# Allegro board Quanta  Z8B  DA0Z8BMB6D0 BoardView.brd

Outline 202.63 x 196.03 mm; copper layers: TOP, SVCC, IN1, IN2, SGND, BOTTOM. Coordinates in mm from the lower left corner of the outline.

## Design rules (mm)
constraint set DEFAULT: min track width 0.127
net group DFP-S10W5(5.25)-T2B: nets VCC_SENSE_R VSS_SENSE_R
net group DFP-S20W5(5.25)-T2B: nets DDCCLK DDCDAT
net group W8-T12B: nets +3V_EC +3V_RTC
net group W80-T12B: nets +5V_HDD +5V_ODD
net group DFP-S3.5(3.75)W5(5.25)-T1B: nets VMA_RDQS0 VMA_RDQS1 VMA_RDQS2 VMA_RDQS4 VMA_RDQS5 VMA_RDQS6 VMA_WDQS0 VMA_WDQS1 VMA_WDQS2 VMA_WDQS4 VMA_WDQS5 VMA_WDQS6
net group DFP-S3.5(3.75)W5(5.25)-T2B: nets C_PEG_TX0 C_PEG_TX1 C_PEG_TX2 C_PEG_TX3 C_PEG_TX4 C_PEG_TX5 C_PEG_TX6 C_PEG_TX7 C_PEG_TX#0 C_PEG_TX#1 C_PEG_TX#2 C_PEG_TX#3 C_PEG_TX#4 C_PEG_TX#5 C_PEG_TX#6 C_PEG_TX#7 PEG_RX0 PEG_RX0#_C PEG_RX0_C PEG_RX1 PEG_RX1#_C PEG_RX1_C PEG_RX2 PEG_RX2#_C PEG_RX2_C PEG_RX3 PEG_RX3#_C PEG_RX3_C PEG_RX4 PEG_RX4#_C PEG_RX4_C PEG_RX5 PEG_RX5#_C PEG_RX5_C PEG_RX6 PEG_RX6#_C PEG_RX6_C PEG_RX7 PEG_RX7#_C PEG_RX7_C PEG_RX#0 PEG_RX#1 PEG_RX#2 PEG_RX#3 PEG_RX#4 PEG_RX#5 PEG_RX#6 PEG_RX#7 PEG_TX0 PEG_TX1 PEG_TX2 PEG_TX3 PEG_TX4 PEG_TX5 PEG_TX6 PEG_TX7 PEG_TX#0 PEG_TX#1 PEG_TX#2 PEG_TX#3 PEG_TX#4 PEG_TX#5 PEG_TX#6 PEG_TX#7
net group DFP-S3.5(3.75)W5(5.25)-T12B: nets VMA_CLK0 VMA_CLK0# VMA_CLK1 VMA_CLK1# VMA_RDQS3 VMA_RDQS7 VMA_WDQS3 VMA_WDQS7
net group DFP-S4.5(4.75)W5(5.25)-2B: nets EDP_TX0#_C EDP_TX0_C EDP_TX1#_C EDP_TX1_C EDP_TXN0 EDP_TXN1 EDP_TXP0 EDP_TXP1 INT_HDMITX0N INT_HDMITX0P INT_HDMITX2N INT_HDMITX2P PCIE_TX4+ PCIE_TX4- USBP1+ USBP1- USBP2+ USBP2- USBP3+ USBP3- USBP5+ USBP5- USBP9+ USBP9-
net group DFP-S4.5(4.75)W5(5.25)-T2B: nets DMI_RXN0 DMI_RXN1 DMI_RXN2 DMI_RXN3 DMI_RXP0 DMI_RXP1 DMI_RXP2 DMI_RXP3 DMI_TXN0 DMI_TXN1 DMI_TXN2 DMI_TXN3 DMI_TXP0 DMI_TXP1 DMI_TXP2 DMI_TXP3 EDP_AUX#_C EDP_AUX_C EDP_AUXN EDP_AUXP FDI_TXN0 FDI_TXN1 FDI_TXP0 FDI_TXP1 GPP_TX4N_LAN GPP_TX4P_LAN INT_HDMICLK+ INT_HDMICLK- INT_HDMITX0N_C INT_HDMITX0P_C INT_HDMITX1N INT_HDMITX1N_C INT_HDMITX1P INT_HDMITX1P_C INT_HDMITX2N_C INT_HDMITX2P_C PCIE_RX3+_WLAN PCIE_RX3-_WLAN PCIE_RX4+_LAN PCIE_RX4-_LAN PCIE_TX3+ PCIE_TX3+_WLAN PCIE_TX3- PCIE_TX3-_WLAN PCIE_TX4+_LAN PCIE_TX4-_LAN SATA_RXN0 SATA_RXN0_C SATA_RXN5 SATA_RXN5_C SATA_RXN5_CN SATA_RXP0 SATA_RXP0_C SATA_RXP5 SATA_RXP5_C SATA_RXP5_CN SATA_TXN0 SATA_TXN0_C SATA_TXN5 SATA_TXN5_C SATA_TXN5_CN SATA_TXP0 SATA_TXP0_C SATA_TXP5 SATA_TXP5_C SATA_TXP5_CN USB3_RXN0 USB3_RXP0 USB3_TXN0 USB3_TXP0 USBP0+ USBP0-
net group DFP-S5.5(5.5)W5(5.25)-1B: nets M_A_CLKN0 M_A_CLKN1 M_A_CLKP0 M_A_CLKP1 M_A_DQSN0 M_A_DQSN1 M_A_DQSN2 M_A_DQSN3 M_A_DQSN4 M_A_DQSN5 M_A_DQSN6 M_A_DQSN7 M_A_DQSP0 M_A_DQSP1 M_A_DQSP2 M_A_DQSP3 M_A_DQSP4 M_A_DQSP5 M_A_DQSP6 M_A_DQSP7
net group DFP-S5.5(5.5)W5(5.25)-2B: nets M_B_CLKN0 M_B_CLKN1 M_B_CLKP0 M_B_CLKP1 M_B_DQSN0 M_B_DQSN1 M_B_DQSN2 M_B_DQSN3 M_B_DQSN4 M_B_DQSN5 M_B_DQSN6 M_B_DQSN7 M_B_DQSP0 M_B_DQSP1 M_B_DQSP2 M_B_DQSP3 M_B_DQSP4 M_B_DQSP5 M_B_DQSP6 M_B_DQSP7
net group DFP-S5W5(5.25)-T12B: nets 2ND_MBCLK 2ND_MBDATA CL_CLK1_WLAN CL_DATA1_WLAN G_MBCLK G_MBCLK_R G_MBDATA G_MBDATA_R SMB_ME0_CLK SMB_ME0_DAT SMB_ME1_CLK SMB_ME1_DAT SMB_PCH_CLK SMB_PCH_DAT WLAN_CLK_SCLK WLAN_CLK_SDATA
net group DFP-S6.5(6.25)W5(5.25)-2B: nets CLK_BUF_CKSSCDN CLK_BUF_CKSSCDP CLK_BUF_CPYCKN CLK_BUF_CPYCKP CLK_BUF_DOT96N CLK_BUF_DOT96P CLK_BUF_EXPN CLK_BUF_EXPP CLK_CPU_BCLKN CLK_CPU_BCLKN_R CLK_CPU_BCLKP CLK_CPU_BCLKP_R CLK_DPLL_NSCLKN CLK_DPLL_NSCLKN_R CLK_DPLL_NSCLKP CLK_DPLL_NSCLKP_R CLK_DPLL_SSCLKN CLK_DPLL_SSCLKP CLK_PCIE_VGA CLK_PCIE_VGA# CLK_PCIE_WLAN#_C CLK_PCIE_WLAN_C CLK_PCIE_XDPN_R CLK_PCIE_XDPP_R
net group DFP-S6.5(6.25)W5(5.25)-T2B: nets CLK_DPLL_SSCLKN_R CLK_DPLL_SSCLKP_R CLK_PCIE_LANN CLK_PCIE_LANP
net group DFP-S15(14.25)W5(5.25)-T2B: nets LAN_MX0+ LAN_MX0- LAN_MX1+ LAN_MX1- LAN_MX2+ LAN_MX2- LAN_MX3+ LAN_MX3- MDI_0+ MDI_0+_C MDI_0- MDI_0-_C MDI_1+ MDI_1+_C MDI_1- MDI_1-_C MDI_2+ MDI_2+_C MDI_2- MDI_2-_C MDI_3+ MDI_3+_C MDI_3- MDI_3-_C
net group DFP-S15W5(5.25)-T12B: nets 27M_XTAL_IN_R 27M_XTAL_OUT LAN_XTAL2 LAN_XTALI RTC_X1 RTC_X2 XTAL25_IN XTAL25_OUT
net group DFP-S15W40-T12B: nets L_SPK+ L_SPK+_1 L_SPK- L_SPK-_1 R_SPK+ R_SPK+_1 R_SPK- R_SPK-_1
net group W4.5(5)-T12B: nets CPU_DRAMRST# CPU_PLTRST# CPU_RST#_R DDR3_DRAMRST# DDR3_DRAMRST#_R H_PECI H_PWRGOOD H_PWRGOOD_R PCH_PECI PCH_SYNCH PCH_THRMTRIP# PM_DRAM_PWRGD PM_DRAM_PWRGD_Q PM_DRAM_PWRGD_R PM_SYNC PM_SYNC_R PM_THRMTRIP#
net group W5(5.25)-2B: nets CRT_BLU CRT_HSYNC_R CRT_VSYNC_R H_CPU_SVIDART# H_CPU_SVIDCLK H_CPU_SVIDDAT H_PROCHOT# HSYNC VSYNC
net group W5(5.25)-12B: nets VR_SVID_ALERT# VR_SVID_CLK VR_SVID_DATA
net group W5(5.25)-T2B: nets A_LAD0_R A_LAD1_R A_LAD2_R A_LAD3_R A_LFRAME#_R ACZ_SDIN CRT_B1 CRT_G1 CRT_GRE CRT_R1 CRT_RED CRTHSYNC CRTVSYNC HDA_BCLK_R HDA_RST#_R HDA_SDO_R HDA_SYNC_R HDMI_DDCCLK_MB HDMI_DDCCLK_SW HDMI_DDCDATA_MB HDMI_DDCDATA_SW LPC_LAD0 LPC_LAD1 LPC_LAD2 LPC_LAD3 LPC_LFRAME# PCH_AZ_CODEC_BITCLK PCH_AZ_CODEC_RST# PCH_AZ_CODEC_SDIN0 PCH_AZ_CODEC_SDOUT PCH_AZ_CODEC_SYNC SATA_RCOMP SD_CLK
net group W5(5.25)-T12B: nets CLK_PCH_PCI3 CLK_PCH_PCI4 CLK_PCI_EC CLK_PCI_FB CLK_PCI_LPC DMIC_CLK_L DMIC_DAT_L DNBSWON# DPWROK DSWVREN EC_PWROK EC_RCIN# EDP_HPD FDI_CSYNC FDI_CSYNC_R FDI_INT GPUT_CLK_L GPUT_DATA_L H_PROCHOT#_R IMVP_PWRGD M_A_DQ0 M_A_DQ1 M_A_DQ2 M_A_DQ3 M_A_DQ4 M_A_DQ5 M_A_DQ6 M_A_DQ7 M_A_DQ8 M_A_DQ9 M_A_DQ10 M_A_DQ11 M_A_DQ12 M_A_DQ13 M_A_DQ14 M_A_DQ15 M_A_DQ16 M_A_DQ17 M_A_DQ18 M_A_DQ19 M_A_DQ20 M_A_DQ21 M_A_DQ22 M_A_DQ23 M_A_DQ24 M_A_DQ25 M_A_DQ26 M_A_DQ27 M_A_DQ28 M_A_DQ29 M_A_DQ30 M_A_DQ31 M_A_DQ32 M_A_DQ33 M_A_DQ34 M_A_DQ35 M_A_DQ36 M_A_DQ37 M_A_DQ38 M_A_DQ39 M_A_DQ40 M_A_DQ41 M_A_DQ42 M_A_DQ43 M_A_DQ44 M_A_DQ45 M_A_DQ46 M_A_DQ47 M_A_DQ48 M_A_DQ49 M_A_DQ50 M_A_DQ51 M_A_DQ52 M_A_DQ53 M_A_DQ54 M_A_DQ55 M_A_DQ56 M_A_DQ57 M_A_DQ58 M_A_DQ59 M_A_DQ60 M_A_DQ61 M_A_DQ62 M_A_DQ63 M_B_DQ0 M_B_DQ1 M_B_DQ2 M_B_DQ3 M_B_DQ4 M_B_DQ5 M_B_DQ6 M_B_DQ7 M_B_DQ8 M_B_DQ9 M_B_DQ10 M_B_DQ11 M_B_DQ12 M_B_DQ13 M_B_DQ14 M_B_DQ15 M_B_DQ16 M_B_DQ17 M_B_DQ18 M_B_DQ19 M_B_DQ20 M_B_DQ21 M_B_DQ22 M_B_DQ23 M_B_DQ24 M_B_DQ25 M_B_DQ26 M_B_DQ27 M_B_DQ28 M_B_DQ29 M_B_DQ30 M_B_DQ31 M_B_DQ32 M_B_DQ33 M_B_DQ34 M_B_DQ35 M_B_DQ36 M_B_DQ37 M_B_DQ38 M_B_DQ39 M_B_DQ40 M_B_DQ41 M_B_DQ42 M_B_DQ43 M_B_DQ44 M_B_DQ45 M_B_DQ46 M_B_DQ47 M_B_DQ48 M_B_DQ49 M_B_DQ50 M_B_DQ51 M_B_DQ52 M_B_DQ53 M_B_DQ54 M_B_DQ55 M_B_DQ56 M_B_DQ57 M_B_DQ58 M_B_DQ59 M_B_DQ60 M_B_DQ61 M_B_DQ62 M_B_DQ63 PCH_APWROK PCH_INVRMEN PCH_JTAG_TCK PCH_JTAG_TCK_R PCH_JTAG_TDI PCH_JTAG_TDI_R PCH_JTAG_TDO PCH_JTAG_TDO_R PCH_JTAG_TMS PCH_JTAG_TMS_R PCH_PWRBTN# PCH_PWROK PCH_RI# PCH_RSMRST# PCH_SLP_A# PCH_SLP_S3# PCH_SLP_S4# PCH_SLP_S5# PCH_SLP_SUS# PCH_SPI_CLK PCH_SPI_CLK_EC PCH_SPI_CS0# PCH_SPI_IO2 PCH_SPI_IO3 PCH_SPI_SI PCH_SPI_SI_EC PCH_SPI_SO PCH_SPI_SO_EC PCI_PLTRST# PCIE_IREF PCIE_RCOMP PCIE_WAKE#_R PCLK_TPM PEGX_RST# PEX_TERMP PLTRST# RSMRST# RTC_RST# SD_CD#_R SD_CDZ SD_CLK_R SD_CMD SD_CMD_R SD_D0/MS_D6 SD_D1/MS_D7 SD_D2/MS_D5 SD_D3/MS_D4 SD_D7/MS_CLK SD_DATA0_R SD_DATA1_R SD_DATA2_R SD_DATA3_R SD_WP/MS_D1 SD_WP_R SLP_A# SLP_S5# SLP_SUS# SM_INTRUDER# SPI_CLK SPI_CS0# SPI_CS0#_UR_ME SPI_SI SPI_SO SRTC_RST# SUSB# SUSC# SYS_PWROK SYS_RESET# TESTMODE USBCOMP XDP_BPM#0 XDP_BPM#1 XDP_BPM#2 XDP_BPM#3 XDP_BPM#4 XDP_BPM#5 XDP_BPM#6 XDP_BPM#7 XDP_DBRST# XDP_TCLK XDP_TDI XDP_TDO XDP_TMS XDP_TRST#
net group W6(6.5)-T12B: nets FBA_CMD0 FBA_CMD1 FBA_CMD2 FBA_CMD3 FBA_CMD4 FBA_CMD5 FBA_CMD6 FBA_CMD7 FBA_CMD8 FBA_CMD9 FBA_CMD10 FBA_CMD11 FBA_CMD12 FBA_CMD13 FBA_CMD14 FBA_CMD15 FBA_CMD16 FBA_CMD17 FBA_CMD18 FBA_CMD19 FBA_CMD20 FBA_CMD21 FBA_CMD22 FBA_CMD23 FBA_CMD24 FBA_CMD25 FBA_CMD26 FBA_CMD27 FBA_CMD28 FBA_CMD29 FBA_CMD30 VMA_DM0 VMA_DM1 VMA_DM2 VMA_DM3 VMA_DM4 VMA_DM5 VMA_DM6 VMA_DM7 VMA_DQ0 VMA_DQ1 VMA_DQ2 VMA_DQ3 VMA_DQ4 VMA_DQ5 VMA_DQ6 VMA_DQ7 VMA_DQ8 VMA_DQ9 VMA_DQ10 VMA_DQ11 VMA_DQ12 VMA_DQ13 VMA_DQ14 VMA_DQ15 VMA_DQ16 VMA_DQ17 VMA_DQ18 VMA_DQ19 VMA_DQ20 VMA_DQ21 VMA_DQ22 VMA_DQ23 VMA_DQ24 VMA_DQ25 VMA_DQ26 VMA_DQ27 VMA_DQ28 VMA_DQ29 VMA_DQ30 VMA_DQ31 VMA_DQ32 VMA_DQ33 VMA_DQ34 VMA_DQ35 VMA_DQ36 VMA_DQ37 VMA_DQ38 VMA_DQ39 VMA_DQ40 VMA_DQ41 VMA_DQ42 VMA_DQ43 VMA_DQ44 VMA_DQ45 VMA_DQ46 VMA_DQ47 VMA_DQ48 VMA_DQ49 VMA_DQ50 VMA_DQ51 VMA_DQ52 VMA_DQ53 VMA_DQ54 VMA_DQ55 VMA_DQ56 VMA_DQ57 VMA_DQ58 VMA_DQ59 VMA_DQ60 VMA_DQ61 VMA_DQ62 VMA_DQ63
net group W7.5(8.5)-T12B: nets M_A_A0 M_A_A1 M_A_A2 M_A_A3 M_A_A4 M_A_A5 M_A_A6 M_A_A7 M_A_A8 M_A_A9 M_A_A10 M_A_A11 M_A_A12 M_A_A13 M_A_A14 M_A_A15 M_A_BS#0 M_A_BS#1 M_A_BS#2 M_A_CAS# M_A_CKE0 M_A_CKE1 M_A_CS#0 M_A_CS#1 M_A_ODT0 M_A_ODT1 M_A_RAS# M_A_WE# M_B_A0 M_B_A1 M_B_A2 M_B_A3 M_B_A4 M_B_A5 M_B_A6 M_B_A7 M_B_A8 M_B_A9 M_B_A10 M_B_A11 M_B_A12 M_B_A13 M_B_A14 M_B_A15 M_B_BS#0 M_B_BS#1 M_B_BS#2 M_B_CAS# M_B_CKE0 M_B_CKE1 M_B_CS#0 M_B_CS#1 M_B_ODT0 M_B_ODT1 M_B_RAS# M_B_WE#
net group W7.5-T12B: nets CS_BST1
net group W10-T12B: nets +G_SEN_PW +PCH_VCCDSW +V1.05M_VCCDUSBSUS +V1.05S_VCC_AXCK_DCB +V1.5S_VCCATS +V1.05S_VCCAUSB +V1.05S_VCCAUX +V1.05S_VCCPCPU +V3.3M_VCCPSPI +V3.3S_ADACBG +V3.3S_VCC_FLEX0 +V3.3S_VCC_FLEX1 +V3.3S_VCCAUBG +V3.3S_VCCPTS +VCC_CPU_XDP +VCC_HDA_IO +VCC_PCH_XDP +VCCAXCK_VRM +VCCCLKF135 +VCCIO_PCH_R +VCCPDSW +VCCPRTCSUS_3P3 +VCCRTCEXT +VCCSST +VGPU_CORE BATLED0# DMI_IREF DMI_RCOMP FB_CAL_PU_GND FDI_IREF FDI_RCOMP ICLK_BIAS ICLK_IREF LINE2-L LINE2-R PCH_VCC_1_1_20 PCH_VCC_1_1_21 PWRLED# RSET SUSLED#
net group W12-T12B: nets +SMDDR_VREF_DIMM PEG_RCOMP SATA_IREF
net group W15-T12B: nets +SM_VREF +V1.05M_VCCSUS +V1.05S_VCC_SSCFF +V1.05S_VCCCLKF100 +V3.3S_VCC_ASEPCI +V3.3S_VCC_FLEX23 +V3.3S_VCC_GIO +V3.3S_VCCPFUSE +VCCA_DAC_1_2 CLK_BUF_REF14 FB_CAL_PD_VDDQ HP_JD# HPL HPL-1 HPL_SYS HPR HPR-1 HPR_SYS LINE1L-VREFO LINE1L_R LINE1R-VREFO LINE1R_R MIC2-VREFO SENSEA SM_RCOMP_0 SM_RCOMP_1 SM_RCOMP_2 SP_PLLVDD
net group W20-T12B: nets +1.05V_GFX +1.5V_WLAN +1.5VA +1.35V_GFX +3V_GFX +3V_RTC_0 +3V_RTC_1 +3V_RTC_2 +3V_TPM_VDD +5VA +AZA_VDD +FB_PLLAVDD +V1.05M_VCCASW +V1.05S_PCH_VCC +V1.05S_VCC_EXP +V1.05S_VCCAPLL_EXP +V1.05S_VCCAPLL_FDI +V1.05S_VCCAPLL_SATA3 +V1.05S_VCCSSCF100 +V1.05S_VCCUSBCORE +V3.3A_VCCPSUS +V3.3A_VCCPUSB +V3.3S_VCCPCORE +VCCA_USBSUS +VCCAPLL_USB3 +VCCIO_OUT_R +VCCIO_PCH +VCCIOA_OUT_R +VREF_CA_CPU +VREFDQ_SA_M3 +VREFDQ_SB_M3 AVDD CFG_RCOMP DDR_VTTREF DVDD DVDD_IO EDP_RCOMP FB_CAL_TERM_GND PEX_PLLVDD TD_IREF VCC_XD VREFC_VMA1 VREFC_VMA3 VREFD_VMA3
net group W25-T12B: nets +VCCIO_OUT +VCCIOA_OUT VCCRTC_3 VCCRTC_4
net group W30-T12B: nets +3VPCU_EC +3VPCU_ECPLL +5V_KB +5V_KB_R +A3VPCU +SMDDR_VREF_DQ0 +SMDDR_VREF_DQ1 CCD_PWR CRTVDD5 ECAGND HDMI_5V LANCT3 SMDDR_VREF_DQ0_M1 SMDDR_VREF_DQ1_M1 TH_FAN_POWER
net group W40-T12B: nets +WL_VDD LCDVCC REGOUT RING2 RING2_R SLEEVE SLEEVE_R VDD10 VDDREG/VDD33
net group W50-T12B: nets +TPVDD
net group W60-T12B: nets +3V_MAIN +DDR_VTT_RUN LANVCC V_BLIGHT
net group W90-T12B: nets USBPWR1

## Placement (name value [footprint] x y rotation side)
BT1  rtc socket  [ML1220-SMT]  70.2 36.11 0 top
C1  1u/6.3v_4  [CC0402]  104.6 178.73 270 top
C2  *2200p/50v_4  [CC0402]  170.97 177.74 270 top
C3  ev@1u/10v_6  [CC0603]  113.77 176.55 180 top
C4  0.1u/10v_4  [CC0402]  104.45 176.52 90 top
C5  *0.1u/10v_4  [CC0402]  105.46 176.52 90 top
C6  0.01u/25v_4  [CC0402]  106.55 176.52 270 top
C7  *0.01u/25v_4  [CC0402]  170.97 175.46 90 top
C8  ev@0.1u/10v_4  [CC0402]  113.95 175.33 0 top
C9  ev@1u/6.3v_4  [CC0402]  113.95 174.19 180 top
C10  1000p/50v_4  [CC0402]  111.89 173.88 0 top
C11  *2.2u/10v_8  [CC0805]  104.95 173.81 270 top
C12  ev@1u/6.3v_4  [CC0402]  113.95 172.92 180 top
C13  *ev@0.022u/25v_4  [CC0402]  162.94 172.84 0 top
C14  0.1u/10v_4_x7r  [CC0402]  111.89 172.69 0 top
C15  ev@1u/6.3v_4  [CC0402]  113.95 171.65 180 top
C16  22u/6.3v_8  [CC0805]  105.64 171.09 0 top
C17  *ev@0.022u/25v_4  [CC0402]  162.94 170.58 180 top
C18  ev@0.1u/10v_4  [CC0402]  136.22 170.1 270 top
C19  ev@0.1u/10v_4  [CC0402]  113.18 169.87 270 top
C20  *1u/6.3v_4  [CC0402]  106.58 169 90 top
C21  *1u/6.3v_4  [CC0402]  108.43 168.88 180 top
C22  *0.1u/10v_4  [CC0402]  111.69 168.09 180 top
C23  ev@1u/6.3v_4  [CC0402]  113.95 165.55 180 top
C24  ev@0.1u/10v_4  [CC0402]  152.09 165.4 270 top
C25  ev@0.1u/10v_4  [CC0402]  113.95 164.28 0 top
C26  ev@4.7u/6.3v_6  [CC0603]  155.48 163.21 90 top
C27  ev@0.1u/10v_4  [CC0402]  152.68 163.19 90 top
C28  ev@1u/10v_6  [CC0603]  153.85 163.11 90 top
C29  ev@1u/6.3v_4  [CC0402]  113.95 163.01 180 top
C30  ev@4.7u/6.3vs_6  [CC0603]  143.39 162.35 90 top
C31  ev@4.7u/6.3vs_6  [CC0603]  153.06 161.22 0 top
C32  ev@22u/6.3v_8  [CC0805]  149.7 161.16 90 top
C33  ev@4.7u/6.3v_6  [CC0603]  142.21 161.16 270 top
C34  ev@0.1u/10v_4  [CC0402]  157.96 161.03 0 top
C35  ev@1u/6.3v_4  [CC0402]  144.17 160.52 180 top
C36  ev@10u/6.3v_6  [CC0603]  113.69 160.47 0 top
C37  ev@4.7u/6.3vs_6  [CC0603]  146.02 160.45 90 top
C38  ev@4.7u/6.3v_6  [CC0603]  147.3 160.44 90 top
C39  ev@1u/10v_6  [CC0603]  158.01 159.81 0 top
C40  ev@0.1u/10v_4  [CC0402]  155.55 159.55 0 top
C41  ev@0.1u/10v_4  [CC0402]  152.76 159.43 180 top
C42  ev@1u/6.3v_4  [CC0402]  144.2 159.41 180 top
C43  ev@10u/6.3v_6  [CC0603]  113.69 159.07 0 top
C44  ev@4.7u/6.3v_6  [CC0603]  149.84 158.8 180 top
C45  ev@4.7u/6.3v_6  [CC0603]  158.01 158.49 0 top
C46  ev@4.7u/6.3vs_6  [CC0603]  142.37 158.39 90 top
C47  ev@0.1u/10v_4  [CC0402]  152.76 158.34 180 top
C48  ev@1u/6.3v_4  [CC0402]  144.22 158.33 180 top
C49  ev@1000p/50v_4  [CC0402]  169.11 158.03 180 top
C50  ev@1u/10v_6  [CC0603]  113.69 157.68 180 top
C51  ev@1000p/50v_4  [CC0402]  163.88 168.98 0 top
C52  ev@4.7u/6.3v_6  [CC0603]  146.71 157.55 0 top
C53  *ev@1000p/50v_4  [CC0402]  165.25 157.55 180 top
C54  ev@4.7u/6.3v_6  [CC0603]  149.84 157.5 180 top
C55  ev@1u/6.3v_4  [CC0402]  144.22 157.29 180 top
C56  ev@22u/6.3vs_6  [CC0603]  155.75 157.16 0 top
C57  ev@22u/6.3vs_6  [CC0603]  153.04 157.12 180 top
C58  ev@0.1u/10v_4  [CC0402]  113.95 156.41 0 top
C59  ev@4.7u/6.3v_6  [CC0603]  141.78 156.1 180 top
C60  ev@4.7u/6.3v_6  [CC0603]  146.71 156.05 0 top
C61  ev@4.7u/6.3v_6  [CC0603]  149.81 155.97 180 top
C62  ev@4.7u/6.3v_6  [CC0603]  153.04 155.83 180 top
C63  ev@4.7u/6.3v_6  [CC0603]  144.25 155.46 90 top
C64  *ev@1000p/50v_4  [CC0402]  158.07 167.53 90 top
C65  ev@4.7u/6.3v_6  [CC0603]  157 155.46 0 top
C66  ev@10u/6.3vs_6  [CC0603]  146.71 154.75 0 top
C67  ev@4.7u/6.3vs_6  [CC0603]  141.63 154.66 180 top
C68  ev@4.7u/6.3v_6  [CC0603]  149.79 154.66 180 top
C69  ev@4.7u/6.3v_6  [CC0603]  157 154.14 0 top
C70  ev@0.1u/10v_4  [CC0402]  114.45 153.1 90 top
C71  ev@0.1u/10v_4  [CC0402]  157.24 152.9 180 top
C72  ev@1u/6.3v_4  [CC0402]  143.63 152.52 90 top
C73  ev@1u/6.3v_4  [CC0402]  145.14 152.52 90 top
C74  ev@1u/6.3v_4  [CC0402]  142.3 152.47 90 top
C75  ev@1u/6.3v_4  [CC0402]  147.07 152.39 90 top
C76  ev@10u/6.3vs_6  [CC0603]  141.51 150.44 0 top
C77  ev@22u/6.3vs_6  [CC0603]  137.67 150.18 270 top
C78  ev@10u/6.3vs_6  [CC0603]  141.51 148.79 0 top
C79  ev@4.7u/6.3v_6  [CC0603]  136.4 146.78 0 top
C80  ev@1u/6.3v_4  [CC0402]  113.95 146.5 180 top
C81  ev@10u/6.3vs_6  [CC0603]  136.4 145.43 0 top
C82  ev@1u/6.3v_4  [CC0402]  113.95 145.23 180 top
C83  ev@0.1u/10v_4  [CC0402]  135.41 144.09 180 top
C84  ev@0.1u/10v_4  [CC0402]  138.1 144.06 180 top
C85  ev@0.1u/10v_4  [CC0402]  113.95 143.96 0 top
C86  ev@0.22u/10v_4  [CC0402]  140.24 143.58 270 top
C87  ev@0.22u/10v_4  [CC0402]  141.25 143.58 270 top
C88  ev@0.22u/10v_4  [CC0402]  143.41 143.58 270 top
C89  ev@0.22u/10v_4  [CC0402]  144.43 143.58 270 top
C90  ev@0.22u/10v_4  [CC0402]  146.59 143.58 270 top
C91  ev@0.22u/10v_4  [CC0402]  147.6 143.58 270 top
C92  ev@0.22u/10v_4  [CC0402]  149.76 143.58 270 top
C93  ev@0.22u/10v_4  [CC0402]  150.78 143.58 270 top
C94  ev@0.1u/10v_4  [CC0402]  135.41 142.82 0 top
C95  ev@1u/6.3v_4  [CC0402]  138.1 142.79 0 top
C96  ev@1u/6.3v_4  [CC0402]  113.95 142.69 180 top
C97  ev@0.1u/10v_4  [CC0402]  135.41 141.55 0 top
C98  *0.1u/10v_4  [CC0402]  165 141.5 270 top
C99  ev@4.7u/6.3v_6  [CC0603]  113.69 141.42 180 top
C100  ev@4.7u/6.3v_6  [CC0603]  138.46 141.39 180 top
C101  ev@22u/6.3vs_6  [CC0603]  135.16 140.28 180 top
C102  ev@22u/6.3vs_6  [CC0603]  113.69 140.02 180 top
C103  ev@0.22u/10v_4  [CC0402]  151.33 139.8 270 top
C104  ev@0.22u/10v_4  [CC0402]  152.52 139.8 270 top
C105  ev@0.22u/10v_4  [CC0402]  141.76 139.77 270 top
C106  ev@0.22u/10v_4  [CC0402]  142.78 139.77 270 top
C107  ev@0.22u/10v_4  [CC0402]  144.93 139.77 270 top
C108  ev@0.22u/10v_4  [CC0402]  145.95 139.77 270 top
C109  ev@0.22u/10v_4  [CC0402]  148.11 139.77 270 top
C110  ev@0.22u/10v_4  [CC0402]  149.13 139.77 270 top
C111  *0.1u/10v_4  [CC0402]  135.11 133.14 0 top
C112  *1000p/50v_4  [CC0402]  100.22 124.62 180 top
C113  *0.1u/10v_4  [CC0402]  100.22 123.47 180 top
C114  0.01u/25v_4  [CC0402]  167.04 118.39 90 top
C115  10u/6.3v_8  [CC0805]  169.45 117 180 top
C116  18p/50v_4  [CC0402]  172.88 117 90 top
C117  10u/6.3v_8  [CC0805]  160.94 115.35 270 top
C118  *10u/6.3v_8  [CC0805]  153.67 113.96 270 top
C120  10p/50v_4  [CC0402]  183.29 111.48 270 top
C121  1u/6.3v_4  [CC0402]  162.26 111.47 270 top
C122  1u/6.3v_4  [CC0402]  161.07 111.41 270 top
C123  1u/6.3v_4  [CC0402]  157.01 111.08 0 top
C124  0.1u/10v_4  [CC0402]  24.29 113.86 90 top
C125  *1u/6.3v_4  [CC0402]  163.65 110.69 270 top
C126  1u/6.3v_4  [CC0402]  166.25 109.66 180 top
C127  *0.1u/10v_4  [CC0402]  25.96 109.62 90 top
C128  *10u/6.3v_8  [CC0805]  151.03 109.34 0 top
C129  0.1u/10v_4  [CC0402]  157.05 109.04 180 top
C130  1u/6.3v_4  [CC0402]  170.25 108.53 180 top
C131  *0.22u/6.3v_4  [CC0402]  10.44 108.53 270 top
C132  0.1u/10v_4  [CC0402]  11.58 108.53 270 top
C133  *0.1u/10v_4  [CC0402]  12.73 108.53 90 top
C134  *220p/50v_4  [CC0402]  13.87 108.53 90 top
C135  1u/6.3v_4  [CC0402]  161.58 108.23 180 top
C136  0.1u/10v_4  [CC0402]  164.02 108.23 180 top
C137  0.1u/10v_4  [CC0402]  166.05 108.23 180 top
C138  *4.7u/6.3v_6  [CC0603]  142.07 107.61 0 top
C139  *10u/6.3v_8  [CC0805]  151.03 107.16 0 top
C140  1u/6.3v_4  [CC0402]  168.72 106.88 270 top
C141  1u/6.3v_4  [CC0402]  161.81 106.68 0 top
C142  1u/6.3v_4  [CC0402]  163.84 106.68 180 top
C143  1u/6.3v_4  [CC0402]  165.87 106.68 0 top
C144  0.1u/10v_4  [CC0402]  84.69 106.27 90 top
C145  *1u/6.3v_4  [CC0402]  155.59 106.26 90 top
C146  *0.1u/16v_4  [CC0402]  194.85 105.73 270 top
C147  *0.1u/16v_4  [CC0402]  195.86 105.73 270 top
C148  0.01u/25v_4  [CC0402]  196.88 105.73 270 top
C149  *1000p/50v_4  [CC0402]  175.62 105.59 0 top
C150  1u/6.3v_4  [CC0402]  152.59 105.63 0 top
C151  1u/6.3v_4  [CC0402]  160.71 105.31 0 top
C152  0.1u/10v_4  [CC0402]  163.36 105.06 180 top
C153  0.1u/10v_4  [CC0402]  165.39 105.06 0 top
C154  0.1u/10v_4  [CC0402]  167.42 104.6 180 top
C155  1u/6.3v_4  [CC0402]  158.66 104.42 0 top
C156  0.1u/10v_4  [CC0402]  29.41 104.13 270 top
C157  0.1u/10v_4  [CC0402]  30.56 104.13 270 top
C158  10u/6.3v_8  [CC0805]  152.52 104.09 0 top
C159  22u/6.3v_8  [CC0805]  172.37 103.53 0 top
C160  1u/6.3v_4  [CC0402]  159.24 103.38 180 top
C161  1u/6.3v_4  [CC0402]  161.27 103.38 0 top
C162  1u/6.3v_4  [CC0402]  163.3 103.38 0 top
C163  1u/6.3v_4  [CC0402]  161.32 102.04 0 top
C164  1u/6.3v_4  [CC0402]  159.29 102.01 180 top
C165  1u/6.3v_4  [CC0402]  163.36 102.01 0 top
C166  1u/6.3v_4  [CC0402]  165.64 102.01 0 top
C167  *15p/50v_4  [CC0402]  198.76 101.8 90 top
C168  0.1u/10v_4  [CC0402]  172.67 101.79 180 top
C169  1u/6.3v_4  [CC0402]  156.32 101.71 0 top
C170  22u/6.3v_8  [CC0805]  104.85 101.7 0 top
C171  10u/6.3v_8  [CC0805]  108.44 101.68 0 top
C172  10u/6.3v_8  [CC0805]  112.09 101.68 180 top
C173  22u/6.3v_8  [CC0805]  115.68 101.67 180 top
C174  10u/6.3v_8  [CC0805]  119.26 101.67 180 top
C175  *10p/50v/cog_4  [CC0402]  23.93 101.54 0 top
C176  *10u/6.3v_8  [CC0805]  148.14 100.65 0 top
C177  0.1u/10v_4  [CC0402]  165.77 100.49 0 top
C178  0.1u/10v_4  [CC0402]  163.58 100.46 0 top
C179  0.01u/25v_4  [CC0402]  160.54 100.44 180 top
C180  *10p/50v/cog_4  [CC0402]  23.8 100.27 0 top
C181  0.1u/10v_4  [CC0402]  158.85 100.05 90 top
C182  0.1u/10v_4  [CC0402]  157.02 100.02 180 top
C183  1u/6.3v_4  [CC0402]  162.06 99.95 270 top
C184  22u/6.3v_8  [CC0805]  104.26 99.61 0 top
C185  10u/6.3v_8  [CC0805]  107.82 99.58 0 top
C186  22u/6.3v_8  [CC0805]  118.48 99.51 0 top
C187  10u/6.3v_8  [CC0805]  111.37 99.51 180 top
C188  22u/6.3v_8  [CC0805]  114.92 99.47 180 top
C189  10p/50v_4  [CC0402]  23.8 98.88 180 top
C190  1u/6.3v_4  [CC0402]  170.59 98.71 180 top
C191  22u/6.3v_8  [CC0805]  104.24 97.44 0 top
C192  10u/6.3v_8  [CC0805]  118.48 97.44 180 top
C193  10u/6.3v_8  [CC0805]  107.81 97.41 0 top
C194  10u/6.3v_8  [CC0805]  111.38 97.4 180 top
C195  22u/6.3v_8  [CC0805]  114.93 97.3 180 top
C196  10p/50v_4  [CC0402]  23.8 96.84 180 top
C197  10u/6.3v_8  [CC0805]  145.29 96.46 90 top
C198  *1u/6.3v_4  [CC0402]  164.57 95.61 90 top
C199  *22u/6.3v_8  [CC0805]  104.25 95.28 0 top
C200  10u/6.3v_8  [CC0805]  118.48 95.28 180 top
C201  *22u/6.3v_8  [CC0805]  111.37 95.27 0 top
C202  *22u/6.3v_8  [CC0805]  107.82 95.25 180 top
C203  *22u/6.3v_8  [CC0805]  114.92 95.12 180 top
C204  1u/6.3v_4  [CC0402]  174.07 93.69 180 top
C205  4.7u/6.3v_6  [CC0603]  23.96 93.62 180 top
C206  *10u/6.3v_8  [CC0805]  118.58 93.14 180 top
C207  *10u/6.3v_8  [CC0805]  111.39 93.11 180 top
C208  *10u/6.3v_8  [CC0805]  104.23 93.11 180 top
C209  *22u/6.3v_8  [CC0805]  107.83 93.08 180 top
C210  *10u/6.3v_8  [CC0805]  114.98 93 0 top
C211  1u/6.3v_4  [CC0402]  172.59 92.5 0 top
C212  *0.1u/25v_6  [CC0603]  192.77 91.61 180 top
C213  1u/6.3v_4  [CC0402]  160.56 89.87 90 top
C214  4.7u/6.3v_6  [CC0603]  32.44 84.91 180 top
C215  *0.1u/10v_4  [CC0402]  180.69 84.82 0 top
C216  *0.1u/10v_4  [CC0402]  183.1 80.02 180 top
C217  *470p/50v_4  [CC0402]  97.23 76.62 0 top
C218  *0.1u/10v_4  [CC0402]  102.47 76.09 270 top
C219  *0.1u/10v_4  [CC0402]  103.66 76.09 270 top
C220  tpm@0.1u/10v_4  [CC0402]  179.49 75.95 0 top
C221  *0.1u/10v_4  [CC0402]  81.03 73.91 0 top
C222  *0.1u/10v_4  [CC0402]  93.27 72.87 180 top
C223  1u/6.3v_4  [CC0402]  99.5 72.13 0 top
C224  1u/6.3v_4  [CC0402]  99.5 70.94 0 top
C225  *0.1u/10v_4  [CC0402]  80.34 67.23 90 top
C226  *1000p/50v_4  [CC0402]  81.59 67.23 90 top
C227  0.1u/10v_4  [CC0402]  167.79 66.49 0 top
C228  0.1u/10v_4  [CC0402]  170.99 65.78 270 top
C229  0.1u/10v_4  [CC0402]  175.18 65.75 270 top
C230  0.047u/10v_4  [CC0402]  83.59 64.94 90 top
C231  *10u/6.3v_8  [CC0805]  187.03 64.79 180 top
C232  *220p/50v_4  [CC0402]  15.44 63.26 270 top
C233  2.2u/6.3v_6  [CC0603]  136.53 61.88 270 top
C234  2.2u/6.3v_6  [CC0603]  75.4 61.67 0 top
C235  0.1u/10v_4  [CC0402]  135.28 61.54 270 top
C236  1u/6.3v_4  [CC0402]  138.87 61.34 180 top
C237  0.1u/10v_4  [CC0402]  165.17 60.47 90 top
C238  0.1u/10v_4  [CC0402]  75.65 60.4 0 top
C239  1u/6.3v_4  [CC0402]  138.87 60.2 180 top
C240  0.1u/10v_4  [CC0402]  186.58 59.41 180 top
C241  10u/6.3v_6  [CC0603]  139.12 58.93 0 top
C242  0.1u/10v_4  [CC0402]  163.12 57.36 0 top
C243  0.1u/10v_4  [CC0402]  162.09 56.22 0 top
C244  *10p/50v_4  [CC0402]  159.84 55.06 180 top
C245  1u/6.3v_4  [CC0402]  165.7 54.89 270 top
C246  *10u/6.3v_6  [CC0603]  139.25 52.83 0 top
C247  0.1u/10v_4  [CC0402]  185.08 52.77 270 top
C248  0.1u/10v_4  [CC0402]  114.81 52.34 180 top
C249  1u/6.3v_4  [CC0402]  110.34 51.89 270 top
C250  1u/6.3v_4  [CC0402]  139 51.56 180 top
C251  10u/6.3v_8  [CC0805]  108.61 51.46 270 top
C252  10u/6.3v_6  [CC0603]  111.53 51.46 90 top
C253  10u/6.3v_6  [CC0603]  98.74 51.44 90 top
C254  10u/6.3v_6  [CC0603]  101.53 51.44 90 top
C255  10u/6.3v_6  [CC0603]  103.56 51.44 90 top
C256  10u/6.3v_8  [CC0805]  106.1 51.44 270 top
C257  1u/6.3v_4  [CC0402]  100.01 51.31 270 top
C258  2.2u/6.3v_6  [CC0603]  114.71 51.08 180 top
C259  1u/6.3v_4  [CC0402]  139 50.42 180 top
C260  0.1u/10v_4  [CC0402]  163.19 50.4 0 top
C261  2.2u/6.3v_6  [CC0603]  134.14 49.68 270 top
C262  2.2u/6.3v_6  [CC0603]  74.08 49.5 0 top
C263  0.1u/10v_4  [CC0402]  163.53 49.33 0 top
C264  10u/6.3v_6  [CC0603]  185.34 49.19 90 top
C265  0.1u/10v_4  [CC0402]  74.2 48.25 0 top
C266  1u/6.3v_4  [CC0402]  138.74 48.13 180 top
C267  1u/6.3v_4  [CC0402]  100.01 47.12 90 top
C268  10u/6.3v_6  [CC0603]  101.53 47.12 270 top
C269  *10u/6.3v_6  [CC0603]  103.56 47.12 270 top
C270  0.1u/10v_4  [CC0402]  134.04 47.12 90 top
C271  *0.1u/16v_4  [CC0402]  189.77 47.06 270 top
C272  0.01u/25v_4  [CC0402]  191.04 47.06 270 top
C273  0.01u/25v_4  [CC0402]  192.31 47.06 270 top
C274  1u/6.3v_4  [CC0402]  138.74 46.99 180 top
C275  10u/6.3v_6  [CC0603]  110.55 46.96 270 top
C276  10u/6.3v_6  [CC0603]  108.39 46.86 270 top
C277  10u/6.3v_8  [CC0805]  105.34 46.74 90 top
C278  1u/6.3v_4  [CC0402]  107.12 46.74 90 top
C279  10u/6.3v_6  [CC0603]  111.9 46.74 270 top
C280  10u/6.3v_6  [CC0603]  113.21 46.73 270 top
C281  10u/6.3v_6  [CC0603]  139 45.72 0 top
C282  10u/6.3v_6  [CC0603]  189 45.15 0 top
C284  *0.1u/16v_4  [CC0402]  192.31 44.65 90 top
C285  1u/6.3v_4  [CC0402]  26.06 43 90 top
C286  *10u/6.3v_6  [CC0603]  138.97 41.17 0 top
C287  100u/6.3v_3528  [CC3528]  191.09 40.45 90 top
C288  1u/6.3v_4  [CC0402]  139.12 39.88 180 top
C289  0.1u/10v_4  [CC0402]  22.66 39.09 0 top
C290  1u/6.3v_4  [CC0402]  99.12 38.86 270 top
C291  1u/6.3v_4  [CC0402]  100.26 38.86 270 top
C292  1u/6.3v_4  [CC0402]  139.12 38.74 180 top
C293  10u/6.3v_6  [CC0603]  104.83 38.66 90 top
C294  10u/6.3v_6  [CC0603]  106.1 38.66 90 top
C295  10u/6.3v_6  [CC0603]  103.56 38.63 90 top
C296  0.1u/10v_4  [CC0402]  114.79 38.63 90 top
C297  2.2u/6.3v_6  [CC0603]  113.48 38.61 90 top
C298  *10u/6.3v_6  [CC0603]  107.42 38.58 90 top
C299  10u/6.3v_8  [CC0805]  101.96 38.45 270 top
C300  0.1u/10v_4  [CC0402]  22.66 37.95 0 top
C301  470p/50v_4  [CC0402]  93.15 34.8 180 top
C302  0.1u/10v_4  [CC0402]  32.96 34.62 270 top
C303  10u/6.3v_4  [CC0402]  34.1 34.62 270 top
C304  100p/50v_4  [CC0402]  25.81 34.61 90 top
C305  1u/10v_4  [CC0402]  26.95 34.61 270 top
C306  0.1u/10v_4  [CC0402]  28.09 34.61 270 top
C307  10u/6.3v_4  [CC0402]  30.25 34.61 270 top
C308  *22p/50v_4  [CC0402]  31.4 34.61 90 top
C309  *0.01u/25v_4  [CC0402]  189.59 34.31 180 top
C310  0.01u/25v_4  [CC0402]  191.8 34.11 0 top
C311  0.01u/25v_4  [CC0402]  191.8 33.09 0 top
C312  *0.01u/25v_4  [CC0402]  189.59 32.91 180 top
C313  0.1u/10v_4  [CC0402]  36.26 32.28 180 top
C314  *0.01u/25v_4  [CC0402]  189.59 30.47 180 top
C315  0.01u/25v_4  [CC0402]  191.8 30.3 0 top
C316  *1000p/50v_4  [CC0402]  17.05 30.17 270 top
C317  0.01u/25v_4  [CC0402]  191.8 29.28 0 top
C318  0.1u/10v_4  [CC0402]  36.94 29.2 180 top
C319  10u/6.3v_4  [CC0402]  24.54 29.15 0 top
C320  *0.01u/25v_4  [CC0402]  189.61 29.08 180 top
C321  1u/6.3v_4  [CC0402]  38.75 27.84 0 top
C322  0.1u/10v_4  [CC0402]  36.59 26.66 180 top
C323  4.7u/6.3v_4  [CC0402]  20.86 25.94 180 top
C324  10u/6.3v_4  [CC0402]  35.71 25.36 180 top
C325  10u/6.3v_4  [CC0402]  32.48 24.22 0 top
C326  1u/10v_4  [CC0402]  32.48 23.2 180 top
C327  0.1u/10v_4  [CC0402]  26.68 22.97 90 top
C328  10u/6.3v_4  [CC0402]  27.85 22.97 90 top
C329  2200p/50v_4  [CC0402]  19.2 22.93 90 top
C330  2.2u/6.3v_4  [CC0402]  30.17 22.87 270 top
C331  10u/6.3v_4  [CC0402]  25.48 22.72 90 top
C332  *100p/50v_4  [CC0402]  175.59 17.04 270 top
C333  *100p/50v_4  [CC0402]  176.61 17.01 270 top
C334  *gs@22p/50v_4  [CC0402]  116.16 16.02 180 top
C335  *1000p/50v_4  [CC0402]  110.14 15.54 270 top
C336  2200p/50v_4  [CC0402]  11.06 12.67 180 top
C337  4.7u/6.3v_4  [CC0402]  11.06 11.4 180 top
C338  *gs@33p/50v_4  [CC0402]  109.48 9.67 270 top
C339  *gs@10u/6.3v_6  [CC0603]  117.76 9.21 180 top
C340  *1000p/50v_4  [CC0402]  12.17 8.84 90 top
C341  *gs@33p/50v_4  [CC0402]  110.64 8.83 270 top
C342  *gs@0.1u/10v_4  [CC0402]  115.47 8.83 90 top
C343  .1u/16v_4  [CC0402]  117.22 181.15 0 bottom
C344  *100p/50v_4  [CC0402]  16.03 26.49 270 top
C345  .1u/16v_4  [CC0402]  114.23 180.84 0 bottom
C346  .1u/16v_4  [CC0402]  117.22 180.13 0 bottom
C347  .1u/16v_4  [CC0402]  114.23 179.82 0 bottom
C348  .1u/16v_4  [CC0402]  117.35 178.76 0 bottom
C349  .1u/16v_4  [CC0402]  117.38 177.46 0 bottom
C350  ev@0.1u/10v_4  [CC0402]  145.85 176.55 90 bottom
C351  *1000p/50v_4  [CC0402]  113.95 175.56 180 bottom
C352  ev@0.1u/10v_4  [CC0402]  147.5 175.1 0 bottom
C353  ev@8.2p/50v_4  [CC0402]  151.69 174.7 180 bottom
C354  ev@8.2p/50v_4  [CC0402]  153.72 174.7 0 bottom
C355  ev@1u/6.3v_4  [CC0402]  113.95 174.44 180 bottom
C356  ev@1u/6.3v_4  [CC0402]  113.95 173.17 180 bottom
C357  ev@1u/6.3v_4  [CC0402]  113.95 171.9 180 bottom
C358  ev@330u_2.5v_3528  [CC3528]  173.38 171.27 270 bottom
C359  ev@0.1u/10v_4  [CC0402]  113.95 170.63 0 bottom
C360  ev@0.1u/10v_4  [CC0402]  113.95 169.36 0 bottom
C361  *ev@0.1u/10v_4  [CC0402]  169.6 164.94 0 bottom
C362  4.7u/25v_8  [CC0805]  109.37 162.5 0 bottom
C363  1000p/50v_4  [CC0402]  111.79 162.5 270 bottom
C364  ev@0.1u/10v_4  [CC0402]  113.44 162.5 270 bottom
C365  ev@1u/6.3v_4  [CC0402]  113.95 159.45 180 bottom
C366  ev@10u/6.3v_6  [CC0603]  113.69 158.06 0 bottom
C367  *ev@0.1u/10v_4  [CC0402]  168.48 156.89 180 bottom
C368  ev@10u/6.3v_6  [CC0603]  113.69 156.41 0 bottom
C369  ev@0.1u/10v_4  [CC0402]  166.5 156.03 90 bottom
C370  ev@0.1u/10v_4  [CC0402]  168.48 155.52 180 bottom
C371  *100p/50v_4  [CC0402]  4.04 12.18 90 top
C372  ev@0.1u/10v_4  [CC0402]  113.95 155.14 0 bottom
C373  ev@1u/6.3v_4  [CC0402]  113.95 153.87 180 bottom
C374  ev@1u/6.3v_4  [CC0402]  113.95 152.6 180 bottom
C375  ev@1u/6.3v_4  [CC0402]  113.95 151.33 180 bottom
C376  ev@0.1u/10v_4  [CC0402]  114.19 148.28 270 bottom
C377  ev@10u/6.3v_6  [CC0603]  113.69 145.23 0 bottom
C378  ev@10u/6.3v_6  [CC0603]  113.69 143.96 0 bottom
C379  ev@1u/6.3v_4  [CC0402]  113.95 142.69 180 bottom
C380  ev@22u/6.3vs_6  [CC0603]  135.41 141.57 180 bottom
C381  ev@10u/6.3v_6  [RC0603]  113.69 141.42 180 bottom
C382  ev@22u/6.3vs_6  [CC0603]  135.41 140.3 180 bottom
C383  ev@4.7u/6.3v_6  [CC0603]  113.69 140.02 180 bottom
C384  ev@10u/6.3vs_6  [CC0603]  131.98 138.19 180 bottom
C385  ev@22u/6.3vs_6  [CC0603]  134.88 137.56 180 bottom
C386  ev@4.7u/6.3v_6  [CC0603]  132.01 136.8 180 bottom
C387  *1000p/50v_4  [CC0402]  191.7 134.64 180 bottom
C388  *22u/6.3v_8  [CC0805]  102.26 126.82 180 bottom
C389  *1000p/50v_4  [CC0402]  172.67 124.88 0 bottom
C390  *22u/6.3v_8  [CC0805]  102.26 124.53 180 bottom
C391  *0.1u/10v_4  [CC0402]  95.38 122.67 0 bottom
C392  ev@0.22u/10v_4  [CC0402]  120.68 122.24 90 bottom
C393  ev@0.22u/10v_4  [CC0402]  121.69 122.24 270 bottom
C394  ev@0.22u/10v_4  [CC0402]  122.96 122.24 90 bottom
C395  ev@0.22u/10v_4  [CC0402]  123.98 122.24 90 bottom
C396  ev@0.22u/10v_4  [CC0402]  125.25 122.24 90 bottom
C397  ev@0.22u/10v_4  [CC0402]  126.27 122.24 90 bottom
C398  ev@0.22u/10v_4  [CC0402]  127.54 122.24 90 bottom
C399  ev@0.22u/10v_4  [CC0402]  128.55 122.24 90 bottom
C400  ev@0.22u/10v_4  [CC0402]  129.82 122.24 90 bottom
C401  ev@0.22u/10v_4  [CC0402]  130.84 122.24 90 bottom
C402  ev@0.22u/10v_4  [CC0402]  132.11 122.24 90 bottom
C403  ev@0.22u/10v_4  [CC0402]  133.12 122.24 90 bottom
C404  ev@0.22u/10v_4  [CC0402]  134.42 122.24 90 bottom
C405  ev@0.22u/10v_4  [CC0402]  135.43 122.24 90 bottom
C406  *4.7u/6.3v_6  [CC0603]  91.85 121.81 0 bottom
C407  *0.1u/10v_4  [CC0402]  95.38 121.59 0 bottom
C408  *10u/6.3v_8  [CC0805]  152.94 121.57 270 bottom
C409  18p/50v_4  [CC0402]  171.12 120.67 90 bottom
C410  ev@0.22u/10v_4  [CC0402]  134.93 119.98 0 bottom
C411  ev@0.22u/10v_4  [CC0402]  134.93 118.97 0 bottom
C412  1u/6.3v_4  [CC0402]  152.94 118.65 270 bottom
C413  *6.8p/50v_4  [CC0402]  163.36 118.52 90 bottom
C414  *6.8p/50v_4  [CC0402]  164.5 118.52 90 bottom
C415  *6.8p/50v_4  [CC0402]  165.51 118.52 90 bottom
C416  0.1u/10v_4  [CC0402]  166.91 118.52 90 bottom
C417  10p/50v_4  [CC0402]  154.85 118.14 0 bottom
C418  10p/50v_4  [CC0402]  159.16 118.14 180 bottom
C419  0.1u/10v_4  [CC0402]  189.01 117.06 0 bottom
C420  *1000p/50v_4  [CC0402]  186.84 116.53 0 bottom
C421  0.1u/10v_4  [CC0402]  149 113.61 0 bottom
C422  0.1u/10v_4  [CC0402]  149 112.59 0 bottom
C423  0.1u/10v_4  [CC0402]  149 111.32 0 bottom
C424  0.1u/10v_4  [CC0402]  149 110.31 0 bottom
C425  10p/50v_4  [CC0402]  176.94 109.82 0 bottom
C426  *10p/50v_4  [CC0402]  10.34 108.76 180 bottom
C427  0.1u/10v_4  [CC0402]  179.25 108.58 0 bottom
C428  *100u/6.3v_3528  [CC3528]  195.38 108.02 270 bottom
C429  0.1u/10v_4  [CC0402]  16.28 107.64 270 bottom
C430  *10p/50v_4  [CC0402]  11.76 107.61 180 bottom
C431  *10u/6.3v_8  [CC0805]  144.92 106.33 270 bottom
C432  10p/50v_4  [CC0402]  11.97 106.27 0 bottom
C433  *0.01u/25v_4  [CC0402]  58.63 106.19 270 bottom
C434  2.2u_6  [CC0603]  64.39 105.25 0 bottom
C435  *0.1u/10v_4  [CC0402]  175.53 104.86 0 bottom
C436  10p/50v_4  [CC0402]  10.47 104.69 180 bottom
C437  0.1u/10v_4  [CC0402]  16.66 104.34 270 bottom
C438  0.01u/25v_4  [CC0402]  64.11 103.9 0 bottom
C439  22u/6.3v_8  [CC0805]  104.26 103.83 0 bottom
C440  10u/6.3v_8  [CC0805]  107.81 103.83 0 bottom
C441  22u/6.3v_8  [CC0805]  111.37 103.83 0 bottom
C442  22u/6.3v_8  [CC0805]  114.92 103.83 180 bottom
C443  22u/6.3v_8  [CC0805]  118.48 103.83 0 bottom
C444  4.7u/6.3v_6  [CC0603]  29.03 103.65 90 bottom
C445  5.6p/16v_4  [CC0402]  9.7 103.55 0 bottom
C446  0.1u/10v_4  [CC0402]  27.74 103.35 90 bottom
C447  5.6p/16v_4  [CC0402]  11.86 102.79 90 bottom
C448  2.2u_6  [CC0603]  64.44 102.61 0 bottom
C449  *0.1u/10v_4  [CC0402]  35.31 102 0 bottom
C450  10u/6.3v_6  [CC0603]  195.15 101.81 90 bottom
C451  22u/6.3v_8  [CC0805]  104.85 101.7 0 bottom
C452  0.01u/25v_4  [CC0402]  196.42 101.69 90 bottom
C453  10u/6.3v_8  [CC0805]  108.45 101.68 0 bottom
C454  22u/6.3v_8  [CC0805]  112.1 101.68 0 bottom
C455  22u/6.3v_8  [CC0805]  119.27 101.67 0 bottom
C456  22u/6.3v_8  [CC0805]  115.67 101.66 180 bottom
C457  0.1u/10v_4  [CC0402]  191.49 101.54 0 bottom
C458  5.6p/16v_4  [CC0402]  11.86 100.75 270 bottom
C459  1u/6.3v_4  [CC0402]  27.48 100.53 90 bottom
C460  4.7u/6.3v_6  [CC0603]  28.63 100.53 270 bottom
C461  10u/6.3v_6  [CC0603]  29.97 100.53 270 bottom
C462  5.6p/16v_4  [CC0402]  9.7 100.15 0 bottom
C463  0.1u/10v_4  [CC0402]  25.96 99.89 180 bottom
C464  22u/6.3v_8  [CC0805]  104.26 99.51 0 bottom
C465  22u/6.3v_8  [CC0805]  107.81 99.51 180 bottom
C466  22u/6.3v_8  [CC0805]  111.37 99.51 0 bottom
C467  10u/6.3v_8  [CC0805]  114.92 99.51 0 bottom
C468  22u/6.3v_8  [CC0805]  118.48 99.51 0 bottom
C469  0.1u/10v_4  [CC0402]  25.96 98.88 180 bottom
C470  5.6p/16v_4  [CC0402]  12.88 98.6 270 bottom
C471  0.1u/10v_4  [CC0402]  30.02 98.37 0 bottom
C472  0.1u/10v_4  [CC0402]  32.06 97.94 90 bottom
C473  0.1u/10v_4  [CC0402]  25.96 97.86 180 bottom
C474  5.6p/16v_4  [CC0402]  9.7 97.81 0 bottom
C475  0.1u/10v_4  [CC0402]  181.63 97.69 90 bottom
C476  22u/6.3v_8  [CC0805]  104.26 97.48 0 bottom
C477  22u/6.3v_8  [CC0805]  107.81 97.48 180 bottom
C478  *22u/6.3v_8  [CC0805]  111.37 97.48 0 bottom
C479  *10u/6.3v_8  [CC0805]  114.92 97.48 0 bottom
C480  *10u/6.3v_8  [CC0805]  118.48 97.48 180 bottom
C481  1u/6.3v_4  [CC0402]  177.42 96.79 90 bottom
C482  0.1u/10v_4  [CC0402]  174.89 96.77 270 bottom
C483  1u/6.3v_4  [CC0402]  176.03 96.77 90 bottom
C484  0.1u/10v_4  [CC0402]  29.26 96.46 90 bottom
C485  0.1u/10v_4  [CC0402]  24.26 96.44 270 bottom
C486  *22u/6.3v_8  [CC0805]  121.4 96.21 90 bottom
C487  0.1u/10v_4  [CC0402]  27.13 96.11 270 bottom
C488  0.1u/10v_4  [CC0402]  28.25 96.08 270 bottom
C489  *22u/6.3v_8  [CC0805]  104.26 95.43 0 bottom
C490  *10u/6.3v_8  [CC0805]  111.37 95.42 180 bottom
C491  10u/6.3v_8  [CC0805]  107.82 95.41 0 bottom
C492  *22u/6.3v_8  [CC0805]  114.92 95.35 180 bottom
C493  *10u/6.3v_8  [CC0805]  118.48 95.35 180 bottom
C494  0.01u/25v_4  [CC0402]  195.85 95.19 0 bottom
C495  18p/50v_4  [CC0402]  176.48 94.96 180 bottom
C496  0.01u/25v_4  [CC0402]  195.85 94.05 0 bottom
C497  18p/50v_4  [CC0402]  176.48 93.54 180 bottom
C498  0.01u/25v_4  [CC0402]  195.85 91.26 0 bottom
C499  0.01u/25v_4  [CC0402]  195.85 90.11 0 bottom
C500  10p/3kv/npo_1808  [CC1808]  27.03 87.9 0 bottom
C501  0.1u/10v_4  [CC0402]  150.38 79.69 270 bottom
C502  tpm@0.1u/10v_4  [CC0402]  183.8 74.11 270 bottom
C503  tpmn@10u/6.3v_4  [CC0402]  185.07 74.11 90 bottom
C504  0.01u/50v/x7r_4  [CC0402]  30.13 73.86 0 bottom
C505  220u/6.3v_6x4.5esr18  [ECAP6D3S]  74.99 72.18 180 bottom
C506  tpm@10u/6.3v_4  [CC0402]  183.8 68.01 270 bottom
C507  tpm@0.1u/10v_4  [CC0402]  185.07 68.01 90 bottom
C508  *kbl@0.01u/25v_4  [CC0402]  153.5 64.89 0 bottom
C509  *kbl@4.7u/6.3v_6  [CC0603]  151.77 64.13 270 bottom
C510  *0.1u/10v_4  [CC0402]  187.68 62.81 90 bottom
C511  *1000p/50v_4  [CC0402]  165.65 62.8 90 bottom
C512  0.1u/10v_4  [CC0402]  166.79 62.8 90 bottom
C513  *1000p/50v_4  [CC0402]  167.94 62.8 270 bottom
C514  *0.1u/10v_4  [CC0402]  174.67 62.68 270 bottom
C515  *0.1u/10v_4  [CC0402]  175.81 62.68 90 bottom
C516  *kbl@2.2u/6.3v_6  [CC0603]  154.97 59.66 180 bottom
C517  0.1u/10v_4  [CC0402]  17.05 56.84 0 bottom
C518  0.1u/10v_4  [CC0402]  17.05 55.57 0 bottom
C519  0.1u/10v_4  [CC0402]  16.99 54.24 0 bottom
C520  0.1u/10v_4  [CC0402]  16.99 53.09 0 bottom
C521  0.1u/10v_4  [CC0402]  16.99 51.82 0 bottom
C522  0.1u/10v_4  [CC0402]  16.99 50.68 0 bottom
C523  0.1u/10v_4  [CC0402]  16.99 49.54 0 bottom
C524  10u/6.3v_6  [CC0603]  170.39 46.93 180 bottom
C525  0.1u/10v_4  [CC0402]  16.99 48.39 0 bottom
C526  0.1u/10v_4  [CC0402]  175.96 47.41 0 bottom
C527  *0.1u/10v_4  [CC0402]  183.3 45.41 180 bottom
C528  0.1u/10v_4  [CC0402]  18.44 42.18 0 bottom
C529  470p/50v_4  [CC0402]  18.44 41.04 0 bottom
C530  10u/6.3v_4  [CC0402]  28.09 34.61 270 bottom
C531  *1u/10v_4  [CC0402]  19.28 32.56 0 bottom
C532  10u/6.3v_4  [CC0402]  36.22 26.61 180 bottom
C533  1u/10v_4  [CC0402]  32.48 24.02 0 bottom
C534  *0.1u/10v_4  [CC0402]  36.86 24.2 270 bottom
C535  *10u/6.3v_6  [CC0603]  44.27 23.08 270 bottom
C536  *0.1u/10v_4  [CC0402]  43 22.83 90 bottom
C537  *10u/6.3v_6  [CC0603]  37.11 22.42 180 bottom
C538  *0.1u/10v_4  [CC0402]  146.99 19.7 0 bottom
C539  0.1u/16v_4  [CC0402]  31.53 19.93 180 bottom
C540  0.1u/10v_4  [CC0402]  31.5 18.74 0 bottom
C541  0.1u/10v_4  [CC0402]  168.35 16.84 180 bottom
C542  *56p/50v_4  [CC0402]  29.85 16.83 270 bottom
C543  4.7u/25v_8  [CC0805]  33.74 16.53 270 bottom
C544  0.1u/10v_4  [CC0402]  31.52 16.33 0 bottom
C545  0.1u/10v_4  [CC0402]  38.51 16.07 0 bottom
C546  4.7u/10v_6  [CC0603]  36.73 15.56 270 bottom
C547  68p/50v_4  [CC0402]  25.5 15.23 0 bottom
C548  0.1u/10v_4  [CC0402]  27.79 15.23 180 bottom
C549  68p/50v_4  [CC0402]  35.46 15.18 270 bottom
C550  2.2u/6.3v_6  [CC0603]  41.43 14.29 180 bottom
C551  0.1u/10v_4  [CC0402]  26.34 14.01 180 bottom
C552  10u/6.3v_6  [CC0603]  41.43 13.02 180 bottom
C553  *56p/50v_4  [CC0402]  26.34 13 0 bottom
C554  *0.1u/10v_4  [CC0402]  169.09 12.5 90 bottom
C555  *56p/50v_4  [CC0402]  26.34 11.98 0 bottom
C556  *56p/50v_4  [CC0402]  26.34 10.97 0 bottom
C557  68p/50v_4  [CC0402]  36.98 10.74 90 bottom
C558  0.1u/16v_4  [CC0402]  38 10.74 90 bottom
C559  2.2u/6.3v_6  [CC0603]  35.84 10.48 270 bottom
C560  *0.1u/10v_4  [CC0402]  169.09 10.08 270 bottom
C561  *56p/50v_4  [CC0402]  26.34 9.95 0 bottom
C562  *56p/50v_4  [CC0402]  28.91 8.65 90 bottom
C563  *68p/50v_4  [CC0402]  102.85 6.77 0 bottom
C564  *68p/50v_4  [CC0402]  110.09 5.86 90 bottom
C565  *68p/50v_4  [CC0402]  108.18 5.23 90 bottom
C566  *68p/50v_4  [CC0402]  106.4 5 180 bottom
C567  10u/6.3v_4  [CC0402]  103.36 3.98 0 bottom
C568  0.1u/10v_4  [CC0402]  106.4 3.83 180 bottom
C569  220u/6.3v/esr35_3528  [CC3528]  18.37 44.77 270 top
C570  470p/50v_4  [CC0402]  18.95 45.15 90 bottom
C715  *22u/6.3v_6  [CC0603]  28.22 42.74 90 top
C716  *0.1u/10v_4  [CC0402]  176.28 169.97 180 top
C717  0.1u/10v_4  [CC0402]  129.69 60.32 90 top
C718  1000p/50v_4  [CC0402]  168.1 152.6 180 top
C719  1000p/50v_4  [CC0402]  148.67 184.02 180 top
C720  0.1u/10v_4  [CC0402]  158.07 157.35 180 top
C721  1000p/50v_4  [CC0402]  156.62 163.19 270 top
C722  0.1u/10v_4  [CC0402]  152.58 178.58 270 top
C723  1000p/50v_4  [CC0402]  162.95 180.79 0 top
C724  0.1u/10v_4  [CC0402]  160.56 163.39 180 top
C725  1000p/50v_4  [CC0402]  60.74 109.49 180 top
C726  0.1u/25v_4  [CC0402]  197.72 176.6 90 top
C727  1000p/50v_4  [CC0402]  44.28 79.85 270 top
C728  0.1u/25v_4  [CC0402]  68.89 114.47 270 bottom
C729  1000p/50v_4  [CC0402]  195.2 164.94 0 top
C730  0.1u/25v_4  [CC0402]  182.22 176.7 0 top
C731  1000p/50v_4  [CC0402]  182.99 170.81 90 top
C732  0.1u/10v_4  [CC0402]  171.33 171.24 90 bottom
C733  1000p/50v_4  [CC0402]  173.03 146.37 90 top
C734  0.1u/25v_4  [CC0402]  181.51 181.58 90 top
C735  1000p/50v_4  [CC0402]  47.12 79.67 270 top
C736  0.1u/25v_4  [CC0402]  140.67 187.04 180 top
C737  1000p/50v_4  [CC0402]  54.28 57.07 270 top
C738  0.1u/10v_4  [CC0402]  185.07 118.26 90 bottom
C739  1000p/50v_4  [CC0402]  19.46 104.97 270 top
C740  0.1u/10v_4  [CC0402]  30.18 61.23 270 bottom
C741  1000p/50v_4  [CC0402]  73.08 79.72 180 top
C742  0.1u/25v_4  [CC0402]  75.21 83.23 180 bottom
C743  1000p/50v_4  [CC0402]  92.05 26.36 180 top
C744  0.1u/10v_4  [CC0402]  119.79 91.1 0 top
C745  1000p/50v_4  [CC0402]  135.18 31.67 0 top
C746  0.1u/10v_4  [CC0402]  190.97 107.61 0 top
C747  1000p/50v_4  [CC0402]  191.9 105.99 90 top
C748  0.1u/10v_4  [CC0402]  186.8 117.98 0 bottom
C749  1000p/50v_4  [CC0402]  43.56 83.91 180 top
C750  0.1u/25v_4  [CC0402]  172.62 182.06 90 top
C751  1000p/50v_4  [CC0402]  73.08 80.92 180 top
C752  0.1u/25v_4  [CC0402]  70.69 95.67 0 top
C753  1000p/50v_4  [CC0402]  135.18 28.11 0 top
C754  0.1u/10v_4  [CC0402]  194.03 107.26 0 top
CN1  sd-card  [SDCARD-5-251301001000-6-11P-SMT]  31.5 16.1 0 top
CN2  50398-04071-001  [GS12401-1011-40P-R-NH-SMT]  108.9 180.83 90 bottom
CN3  fan_3p  [HS8803F-3P-L]  53.88 109.55 90 bottom
CN4  pwr_4p  [50503-0040N-V01-4P-L]  35.5 106.75 0 bottom
CN5  crt conn  [DSUB-070546FR015S265ZR-15P-V]  5.51 106.1 270 bottom
CN6  c185q2-11311-l  [SATA-C185Q2-11311-L-13P-R]  200.1 98.2 270 bottom
CN7  lan_rj45  [RJ45-C100JH-10805-L-8P]  6.58 75.58 90 bottom
CN8  *kbl@kb_backlight  [50503-0040N-V01-4P-L]  155.85 70.65 270 bottom
CN9  hdmi connector  [HDMI-2HE1638-000111F-19P]  1.9 55.6 90 bottom
CN10  mini-card1  [MIPCI-800055FB052GX00PL-52P-SMT]  176.5 55.12 180 bottom
CN11  hdd conn  [HDD-193204-1-22P-R]  197.75 43.8 270 bottom
CN12  usb3.0 conn  [USB-C19083-90905-L-9P]  4.77 36.1 90 bottom
CN13  *sata_conn  [51553-01041-001-10P-L]  187.61 27.78 0 bottom
CN14  kb_conn  [88502-260N-26P-L-SMT]  166.5 25.05 0 bottom
CN15  combojack  [AUDIO-313301-1-6P]  4.26 20.14 90 bottom
CN16  fingerprint/b  [196479-06041-3-6P-L]  144.93 14.9 180 bottom
CN17  function/b  [50501-02401-001-24P-L]  186.05 15.59 270 bottom
CN18  is conn  [196297-06021-3-6P-L]  159.8 14.85 180 bottom
CN19  spk_conn_4p  [50273-0040L-001-4P-L]  106.78 10.2 0 bottom
CP1  *100p/50vx4  [8P4R]  153.67 22.24 0 top
CP2  *100p/50vx4  [8P4R]  157.51 20.01 0 top
CP3  *100p/50vx4  [8P4R]  161.44 20.01 0 top
CP4  *100p/50vx4  [8P4R]  165.51 20.01 0 top
CP5  *100p/50vx4  [8P4R]  169.45 20.01 0 top
CP6  *100p/50vx4  [8P4R]  173.51 20.01 0 top
D1  1n4148ws  [DSM]  109.29 155.14 90 top
D2  *bs4200n-c_1206  [CC1206]  21.36 88.46 180 top
D3  rb500v-40  [DSM]  189.17 86.63 270 top
D4  rb500v-40  [DSM]  23.14 64.03 0 top
D5  *az5125-01j  [RC0402]  15.39 61.16 270 top
D6  rb500v-40  [DSM]  190.8 57.09 180 top
D7  rb500v-40  [DSM]  23.14 54.26 0 top
D8  rb500v-40  [DSM]  190.8 53.03 180 top
D9  rb500v-40  [DSM]  190.8 51.12 180 top
D10  rb500v-40  [DSM]  190.8 49.22 180 top
D11  sdmk0340l-7-f  [DSMV]  159.7 47.2 180 top
D12  rb500v-40  [DSM]  29.11 38.8 0 top
D13  rb500v-40  [DSM]  36.98 38.04 0 top
D14  rb500v-40  [DSM]  29.11 36.77 0 top
D15  rb500v-40  [DSM]  36.98 36.01 0 top
D16  tvs az5125-01h.r7g  [D-SOD523-1_2X0_8-0_65H]  15.88 29.43 90 top
D17  vport 0402 151 mv05  [RC0402]  18.19 22.93 90 top
D18  *gs@rb500v-40  [DSM]  118.83 15.41 270 top
D19  vport 0402 151 mv05  [RC0402]  8.88 12.67 0 top
D20  tvs az5125-01h.r7g  [D-SOD523-1_2X0_8-0_65H]  4.04 8.96 270 top
D21  *bs4200n-c_1812  [CC1812]  19.77 91.1 90 bottom
D22  bat54c  [SOT323_213-2_1-1_3-2N7002W]  182.4 89.86 270 bottom
D23  rb501v-40  [DSM]  19.46 108.27 270 top
D24  vport 0402 151 mv05  [RC0402]  18.24 30.17 270 top
HOLE1  *hg-tc394bc217d118p2  [HG-TC394BC217D118P2]  114 193.7 0 top
HOLE2  *hg-tr299x327bc315d118p2  [HG-TR299X327BC315D118P2]  198.5 191.6 0 top
HOLE3  *hg-tc394bc315d118p2  [HG-TC394BC315D118P2]  146.9 190.6 0 top
HOLE4  iv@h-tc236i140bc266d140p2  [H-TC236I140BC266D140P2]  122.51 182.53 180 bottom
HOLE5  *h-tc276bc217d118p2  [H-TC276BC217D118P2]  93.5 138.1 0 top
HOLE6  iv@h-tc236i140bc266d140p2  [H-TC236I140BC266D140P2]  170.88 134.17 180 bottom
HOLE7  *h-tc315i158bc197d158p2  [H-TC315I158BC197D158P2]  109.41 126.85 0 top
HOLE8  *hg-c315d189p2  [HG-C315D189P2]  197.5 118.1 0 top
HOLE9  *h-tsbc217d118p2  [H-Z8B-1]  12 115.1 0 top
HOLE10  *spad-c236nsnp  [SPAD-C236NSNP]  42.5 104.5 0 top
HOLE11  *spad-c236nsnp  [SPAD-C236NSNP]  184.43 99.4 0 top
HOLE12  *hg-tc276bc315d118p2  [HG-TC276BC315D118P2]  12.5 91.1 0 top
HOLE13  *h-c102d102n  [H-C102D102N]  8 86.6 0 top
HOLE14  *h-tc315i158bc197d158p2  [H-TC315I158BC197D158P2]  143.16 85.79 0 top
HOLE15  *h-tc315i158bc197d158p2  [H-TC315I158BC197D158P2]  83.32 80.56 0 top
HOLE16  *h-zq0-1  [H-ZQ0-1]  196.9 79.8 0 top
HOLE17  h-tc197bc217d140p2  [H-TC217BC197D140P2]  188.6 79.1 180 bottom
HOLE18  *h-ts315i118bc315d118p2  [H-TS315I118BC315D118P2]  65 62.1 0 top
HOLE19  *o-z8b-1  [O-Z8B-1]  166.5 35.25 0 top
HOLE20  *h-c177d177n  [H-C177D177N]  151.7 17.6 0 top
HOLE21  *hg-tc276bc315d118p2  [HG-TC276BC315D118P2]  84.17 5.5 0 top
HOLE22  *hg-tc276bc315d118p2  [HG-TC276BC315D118P2]  7.5 5.5 0 top
HOLE24  *h-c177d177n  [H-C177D177N]  97.5 5.3 0 top
HOLE25  *hg-c276d118p2  [HG-C276D118P2]  195.1 4.5 0 top
J2  *jump  [SOLDERJUMPER-2]  126.9 27.37 180 bottom
JDIM1  ddr3-dimm1_h=9.2_std  [DDR-DDRSK-20401-TP8D-204P-LDV]  105.7 55.8 0 bottom
JDIM2  ddr3-dimm0_h=5.2_std  [DDR-DS2SK-20401-TP4B-STD-204P]  105.7 42.9 0 bottom
L1  ev@blm15px181sn1d  [RC0402]  153.69 154.17 270 top
L2  ev@blm15px331sn1d  [RC0402]  154.84 154.17 90 top
L3  ev@blm15px331sn1d  [RC0402]  135.41 139.01 180 top
L4  blm15px181sn1d  [RC0402]  169.07 118.77 180 top
L5  10uh/100ma_8  [RC0805]  157.99 117.11 0 top
L6  *1uh/25ma_6  [RC0603]  149.4 113.96 90 top
L7  *10uh/100ma_8  [RC0805]  147.25 110.69 180 top
L8  *10uh/100ma_8  [RC0805]  145.29 100.88 90 top
L9  blm15ag121sn1d(120,500ma)_4  [RC0402]  167.79 65.22 0 top
L10  blm15ag121sn1d(120,500ma)_4  [RC0402]  186.58 60.6 180 top
L12  blm15ag121sn1d(120,500ma)_4  [RC0402]  186.17 52.77 270 top
L16  0_6  [RC0603]  21.16 27.25 180 top
L17  80ohm@100mhz  [RC0402]  18.7 25.98 0 top
L18  80ohm@100mhz  [RC0402]  7.09 12.18 270 top
L19  0_6  [RC0603]  13.45 11.37 180 top
L22  0_6  [RC0603]  150.4 120.55 180 bottom
L23  *1uh/25ma_6  [RC0603]  142.5 105.78 270 bottom
L24  4.7uh  [L3_2X2_5-3_2]  25.45 102.81 270 bottom
L25  blm15bb470sn1d  [RC0402]  9.7 102.46 0 bottom
L26  blm15bb470sn1d  [RC0402]  9.7 101.29 0 bottom
L27  blm15bb470sn1d  [RC0402]  9.7 98.98 0 bottom
L28  hcb2012kf220t60/6a/22ohm_8  [RC0805]  40.54 22.62 0 bottom
L29  *0_6  [RC0603]  168.25 15.55 180 bottom
L30  *2.2_6  [RC0603]  168.25 14.15 0 bottom
L32  blm18pg121sn  [RC0603]  39.14 10.48 90 bottom
L33  2.2_6  [RC0603]  168.28 18.13 0 bottom
LED1  power led  [LED19-123-Y2ST1D-C30-2T-4P]  62.4 5.4 90 top
LED2  power led  [LED19-123-Y2ST1D-C30-2T-4P]  70.4 5.4 90 top
NOREF  -  []  45.25 -27.04 0 top
NOREF#2  -  [unnamed#2]  103.28 188.77 0 top
NOREF#3  -  []  113.36 -40.56 0 top
NOREF#4  -  [unnamed#2]  16.97 20.31 0 top
NOREF#5  -  [unnamed#2]  189.26 7.13 0 top
NOREF#6  -  []  90.48 17.95 0 top
NOREF#7  -  [unnamed#2]  103.33 185.69 180 bottom
NOREF#8  -  []  51.74 11.12 180 bottom
NOREF#9  -  [unnamed#2]  179.4 10.86 180 bottom
NOREF#10  -  [unnamed#2]  17.81 11.19 180 bottom
PC1  0.1u/50v_6  [CC0603]  193.19 176.6 0 top
PC2  2200p/50v_6  [CC0603]  193.19 174.95 0 top
PC3  0.1u/50v_6  [CC0603]  187.63 174.11 180 top
PC4  0.1u/50v_6  [CC0603]  183.75 183.33 270 top
PC5  0.1u/50v_6  [CC0603]  195.23 175.96 90 top
PC6  2200p/50v_6  [CC0603]  196.52 175.96 270 top
PC7  0.1u/50v_6  [CC0603]  159.44 181.53 270 top
PC8  0.1u/50v_6  [CC0603]  160.79 181.53 90 top
PC9  2200p/50v_6  [CC0603]  171.48 182.06 270 top
PC10  0.47u/25v_6  [CC0603]  162.82 184.68 0 bottom
PC11  0.1u/50v_6  [CC0603]  160.13 182.24 180 bottom
PC12  1u/16v_6  [CC0603]  162.06 189.3 270 bottom
PC13  0.1u/25v_4  [CC0402]  151 182.42 180 bottom
PC14  4.7u/25v_8  [CC0805]  169.88 182.14 90 top
PC15  47n/50v_6  [CC0603]  163.81 188.51 270 top
PC16  0.1u/50v_6  [CC0603]  173.53 189.88 0 top
PC17  10u/25v_8  [CC0805]  178.08 181.81 90 bottom
PC18  2200p/50v_6  [CC0603]  176.05 190.44 180 bottom
PC19  10u/25v_8  [CC0805]  176.05 188.66 0 bottom
PC20  *100p/50v_4  [CC0402]  173.86 191.1 180 top
PC21  0.1u/25v_4  [CC0402]  158.32 190.59 90 top
PC22  *680p/50v_6  [CC0603]  169.57 189.73 270 top
PC23  0.1u/25v_4  [CC0402]  158.4 189.02 180 top
PC24  0.1u/25v_4  [CC0402]  157.15 190.59 90 top
PC25  0.01u/25v_4  [CC0402]  154.84 187.83 180 bottom
PC26  *47p/50v_4  [CC0402]  185.5 190.57 90 top
PC27  *47p/50v_4  [CC0402]  184.38 190.57 90 top
PC28  100p/50v_4  [CC0402]  197.72 174.08 90 top
PC29  33u/25v_6x4.5  [ECAP6_3X6_1-7_2]  45.98 40.43 0 bottom
PC30  4.7u/25v_8  [CC0805]  43.08 70.17 90 bottom
PC31  2200p/50v_6  [CC0603]  44.86 70.17 270 bottom
PC32  10u/6.3v_6  [CC0603]  46.59 60.22 0 top
PC33  0.1u/25v_4  [CC0402]  45.75 58.87 0 top
PC34  4.7u/6.3v_6  [CC0603]  37.65 55.7 0 top
PC35  2200p/50v_6  [CC0603]  43.36 51.68 90 bottom
PC36  4.7u/25v_8  [CC0805]  41.61 51.68 270 bottom
PC37  0.1u/50v_6  [CC0603]  43.11 56.97 180 bottom
PC38  0.1u/50v_6  [CC0603]  43.13 62.81 0 bottom
PC39  220u/6.3v_6x4.2  [ECAP6_3X6_1-7_2]  54.13 64.43 270 bottom
PC40  0.1u/50v_6  [CC0603]  46.59 61.56 0 top
PC41  0.1u/50v_6  [CC0603]  60.73 49.85 0 bottom
PC42  220u/6.3v_6x4.2  [ECAP6_3X6_1-7_2]  54.26 57.22 270 bottom
PC43  *680p/50v_6  [CC0603]  51.74 52.6 0 top
PC44  *680p/50v_6  [CC0603]  53.01 68.88 0 top
PC45  0.1u/50v_6  [CC0603]  40.8 66.59 90 top
